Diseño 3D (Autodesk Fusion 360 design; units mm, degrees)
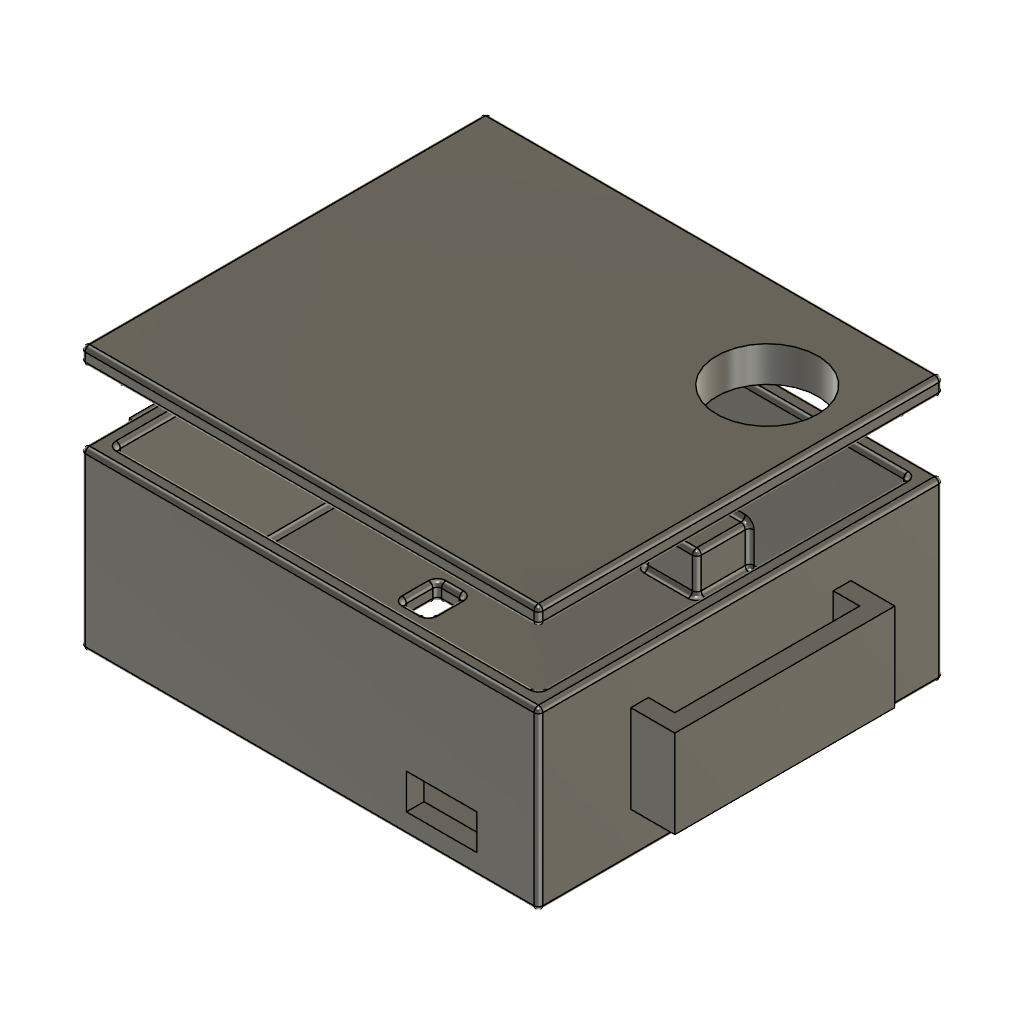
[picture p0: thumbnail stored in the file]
part number: 2026-10-19-01-26-55-343
sketch "Boceto1" plane through (0, 0, 0) normal (0, 0, 1) x axis (1, 0, 0)
  line L1 (-26, -23) -> (26, -23)
  line L2 (-26, 23) -> (-26, -23)
  line L3 (26, 23) -> (-26, 23)
  line L4 (26, -23) -> (26, 23)
  line L5 (-26, 23) -> (26, -23)
  line L6 (26, 23) -> (-26, -23)
  point P6 (0, 0)
  point P1 (0, 0)
  point P4 (-26, 23)
  point P5 (26, 23)
  point P3 (-26, -23)
  horizontal L1
  perpendicular L1 L2
  parallel L1 L3
  parallel L2 L4
  coincident L5 P6
  coincident L6 P6
  coincident P1 P6
  dimension "d1" distance P4 P5 = 52
  dimension "d2" distance P3 P4 = 46
extrude "Extruir1" new body sketch "Boceto1" profile of L1 L2 L3 L4 along normal blind 20
shell "Vaciado" innerThickness 2
sketch "Boceto2" plane through (0, 0, 2) normal (0, 0, 1) x axis (-1, 0, 0)
  line L1 (24, -21) -> (-24, -21)
  line L2 (24, 21) -> (24, -21)
  line L3 (-24, 21) -> (24, 21)
  line L4 (-24, -21) -> (-24, 21)
  line L5 (2, 1.5) -> (-2, 1.5)
  line L6 (2, -1.5) -> (2, 1.5)
  line L7 (-2, -1.5) -> (2, -1.5)
  line L8 (-2, 1.5) -> (-2, -1.5)
  line L9 (2, -1.5) -> (-2, 1.5)
  line L10 (-2, -1.5) -> (2, 1.5)
  point P10 (0, 0)
  point P1 (0, 0)
  point P8 (2, -1.5)
  point P9 (-2, -1.5)
  point P7 (2, 1.5)
  horizontal L5
  perpendicular L5 L6
  parallel L5 L7
  parallel L6 L8
  coincident L9 P10
  coincident L10 P10
  coincident P1 P10
  dimension "d6" distance P8 P9 = 4
  dimension "d7" distance P7 P8 = 3
sketch "Boceto3" plane through (0, 0, 2) normal (0, 0, 1) x axis (-1, 0, 0)
  line L1 (24, -21) -> (-24, -21)
  line L2 (24, 21) -> (24, -21)
  line L3 (-24, 21) -> (24, 21)
  line L4 (-24, -21) -> (-24, 21)
  line L5 (18, -21) -> (24, -21)
  line L6 (18, -15) -> (18, -21)
  line L7 (24, -15) -> (18, -15)
  line L8 (24, -21) -> (24, -15)
  point P3 (24, -21)
  point P6 (24, -21)
  point P7 (18, -21)
  point P9 (24, -15)
  horizontal L5
  vertical L6
  horizontal L7
  vertical L8
  coincident P3 P6
  dimension "d10" distance P6 P7 = 6
  dimension "d11" distance P6 P9 = 6
sketch "Boceto4" plane through (0, 0, 2) normal (0, 0, 1) x axis (-1, 0, 0)
  line L1 (18, 21) -> (24, 21)
  line L2 (18, 15) -> (18, 21)
  line L3 (24, 15) -> (18, 15)
  line L4 (24, 21) -> (24, 15)
  point P2 (24, 21)
  point P3 (18, 21)
  point P5 (24, 15)
  horizontal L1
  vertical L2
  horizontal L3
  vertical L4
  dimension "d12" distance P2 P3 = 6
  dimension "d13" distance P2 P5 = 6
sketch "Boceto5" plane through (0, 0, 2) normal (0, 0, 1) x axis (-1, 0, 0)
sketch "Boceto8" plane through (0, 0, 2) normal (0, 0, 1) x axis (-1, 0, 0)
  line L1 (-24, 21) -> (24, 21)
  line L2 (-24, -21) -> (-24, 21)
  line L3 (24, -21) -> (-24, -21)
  line L4 (24, 21) -> (24, -21)
  line L5 (7.5, -2) -> (10.5, -2)
  line L6 (7.5, 2) -> (7.5, -2)
  line L7 (10.5, 2) -> (7.5, 2)
  line L8 (10.5, -2) -> (10.5, 2)
  point P8 (10.5, -2)
  point P9 (7.5, -2)
  point P11 (10.5, 2)
  horizontal L5
  vertical L6
  horizontal L7
  vertical L8
  dimension "d16" distance P8 P9 = 3
  dimension "d17" distance P8 P11 = 4
  dimension "d19" distance L4 L8 = 13.5
extrude "Extruir4" cut sketch "Boceto8" profile of L5 L6 L7 L8 against normal blind 2
sketch "Boceto9" plane through (0, 0, 2) normal (0, 0, 1) x axis (-1, 0, 0)
  line L1 (7.5, 2) -> (7.5, -2)
  line L2 (10.5, 2) -> (7.5, 2)
  line L3 (10.5, -2) -> (10.5, 2)
  line L4 (7.5, -2) -> (10.5, -2)
  line L5 (24, -21) -> (-24, -21)
  line L6 (24, 21) -> (24, -21)
  line L7 (-24, 21) -> (24, 21)
  line L8 (-24, -21) -> (-24, 21)
  line L9 (18, -21) -> (24, -21)
  line L10 (18, -15) -> (18, -21)
  line L11 (24, -15) -> (18, -15)
  line L12 (24, -21) -> (24, -15)
  point P7 (24, -21)
  point P10 (24, -21)
  horizontal L9
  vertical L10
  horizontal L11
  vertical L12
  coincident P7 P10
sketch "Boceto10" plane through (0, 0, 2) normal (0, 0, 1) x axis (-1, 0, 0)
  line L1 (18, 21) -> (24, 21)
  line L2 (18, 15) -> (18, 21)
  line L3 (24, 15) -> (18, 15)
  line L4 (24, 21) -> (24, 15)
  horizontal L1
  vertical L2
  horizontal L3
  vertical L4
sketch "Boceto11" plane through (0, 0, 2) normal (0, 0, 1) x axis (-1, 0, 0)
  line L1 (-6, -21) -> (0, -21)
  line L2 (-6, -15) -> (-6, -21)
  line L3 (0, -15) -> (-6, -15)
  line L4 (0, -21) -> (0, -15)
  line L5 (18, -15) -> (18, -21)
  horizontal L1
  vertical L2
  horizontal L3
  vertical L4
  dimension "d23" distance L4 L5 = 18
sketch "Boceto12" plane through (0, 0, 2) normal (0, 0, 1) x axis (-1, 0, 0)
  line L1 (0, 21) -> (-6, 21)
  line L2 (0, 15) -> (0, 21)
  line L3 (-6, 15) -> (0, 15)
  line L4 (-6, 21) -> (-6, 15)
  line L5 (18, 15) -> (18, 21)
  horizontal L1
  vertical L2
  horizontal L3
  vertical L4
  dimension "d24" distance L2 L5 = 18
extrude "Extruir5" add blind 4.5
sketch "Boceto14" plane through (0, 0, 2) normal (0, 0, 1) x axis (-1, 0, 0)
  line L1 (0, 15) -> (0, 21)
  line L2 (-6, 15) -> (0, 15)
  line L3 (-6, 21) -> (-6, 15)
  line L4 (-24, 21) -> (-6, 21)
  line L5 (-24, -21) -> (-24, 21)
  line L6 (-6, -21) -> (-24, -21)
  line L7 (-6, -15) -> (-6, -21)
  line L8 (0, -15) -> (-6, -15)
  line L9 (0, -21) -> (0, -15)
  line L10 (18, -21) -> (0, -21)
  line L11 (18, -15) -> (18, -21)
  line L12 (24, -15) -> (18, -15)
  line L13 (24, 15) -> (24, -15)
  line L14 (18, 15) -> (24, 15)
  line L15 (18, 21) -> (18, 15)
  line L16 (0, 21) -> (18, 21)
  line L17 (7.5, 2) -> (7.5, -2)
  line L18 (10.5, 2) -> (7.5, 2)
  line L19 (10.5, -2) -> (10.5, 2)
  line L20 (7.5, -2) -> (10.5, -2)
  line L21 (-10, -21) -> (-24, -21)
  line L22 (-10, -3) -> (-10, -21)
  line L23 (-24, -3) -> (-10, -3)
  line L24 (-24, -21) -> (-24, -3)
  point P7 (-24, -21)
  point P22 (-24, -21)
  point P23 (-10, -21)
  horizontal L21
  vertical L22
  horizontal L23
  vertical L24
  coincident P7 P22
  dimension "d29" distance P22 P23 = 14
extrude "Extruir6" add sketch "Boceto14" profile of L5 L6 L21 L22 L23 L24 along normal blind 3
sketch "Boceto16" plane through (0, 0, 20) normal (0, 0, 1) x axis (-1, 0, 0)
  line L1 (-24, 21) -> (-24, -21)
  line L2 (24, 21) -> (-24, 21)
  line L3 (24, -21) -> (24, 21)
  line L4 (-24, -21) -> (24, -21)
  line L5 (26, -23) -> (-26, -23)
  line L6 (26, 23) -> (26, -23)
  line L7 (-26, 23) -> (26, 23)
  line L8 (-26, -23) -> (-26, 23)
extrude "Extruir7" new body sketch "Boceto16" profile of L1 L2 L3 L4 against normal blind 2
extrude "Extruir8" add sketch "Boceto16" along normal blind 2
fillet "Empalme" radius 0.5
move "Desplazar"
sketch "Boceto17" plane through (0, 0, 30) normal (0, 0, 1) x axis (-1, 0, 0)
  line L1 (25.5, 22.5) -> (25.5, -22.5)
  line L2 (-25.5, 22.5) -> (25.5, 22.5)
  line L3 (-25.5, -22.5) -> (-25.5, 22.5)
  line L4 (25.5, -22.5) -> (-25.5, -22.5)
  circle C1 centre (-17, -12) radius 5.75
  dimension "d38" diameter C1 = 11.5
extrude "Extruir9" cut sketch "Boceto17" profile of C1 against normal blind 5
sketch "Boceto18" plane through (26, 0, 0) normal (1, 0, 0) x axis (0, 1, 0)
  line L1 (22.5, 19.5) -> (22.5, 0.5)
  line L2 (-22.5, 19.5) -> (22.5, 19.5)
  line L3 (22.5, 0.5) -> (-22.5, 0.5)
  line L4 (12.5, 15) -> (-12.5, 15)
  line L5 (12.5, 5) -> (12.5, 15)
  line L6 (-12.5, 5) -> (12.5, 5)
  line L7 (-12.5, 15) -> (-12.5, 5)
  point P6 (-12.5, 15)
  point P7 (12.5, 15)
  point P9 (-12.5, 5)
  horizontal L4
  vertical L5
  horizontal L6
  vertical L7
  dimension "d41" distance P6 P7 = 25
  dimension "d43" distance L2 L4 = 4.5
  dimension "d44" distance P6 P9 = 10
  dimension "d45" distance L1 L5 = 10
extrude "Extruir10" add sketch "Boceto18" profile of L4 L5 L6 L7 along normal blind 5
sketch "Boceto21" plane through (0, 0, 15) normal (0, 0, 1) x axis (-1, 0, 0)
  line L1 (-26, 12.5) -> (-26, -12.5)
  line L2 (-31, 12.5) -> (-26, 12.5)
  line L3 (-31, -12.5) -> (-31, 12.5)
  line L4 (-26, -12.5) -> (-31, -12.5)
  line L5 (-29, -10.5) -> (-26, -10.5)
  line L6 (-29, 10.5) -> (-29, -10.5)
  line L7 (-26, 10.5) -> (-29, 10.5)
  line L8 (-26, -10.5) -> (-26, 10.5)
  point P6 (-26, -10.5)
  point P7 (-29, -10.5)
  point P9 (-26, 10.5)
  horizontal L5
  vertical L6
  horizontal L7
  vertical L8
  coincident L1 P6
  dimension "d48" distance P6 P7 = 3
  dimension "d49" distance P6 P9 = 21
  dimension "d50" distance L4 L5 = 2
extrude "Extruir11" cut sketch "Boceto21" profile of L1 L5 L6 L7 L8 against normal blind 11
sketch "Boceto22" plane through (-26, 0, 0) normal (-1, 0, 0) x axis (0, -1, 0)
  line L1 (22.5, 0.5) -> (-22.5, 0.5)
  line L2 (22.5, 19.5) -> (22.5, 0.5)
  line L3 (-22.5, 19.5) -> (22.5, 19.5)
  line L4 (-22.5, 0.5) -> (-22.5, 19.5)
  line L5 (12.5, 15) -> (-12.5, 15)
  line L6 (12.5, 5) -> (12.5, 15)
  line L7 (-12.5, 5) -> (12.5, 5)
  line L8 (-12.5, 15) -> (-12.5, 5)
  point P6 (-12.5, 15)
  point P7 (12.5, 15)
  point P9 (-12.5, 5)
  horizontal L5
  vertical L6
  horizontal L7
  vertical L8
  dimension "d53" distance P6 P7 = 25
  dimension "d54" distance P6 P9 = 10
  dimension "d55" distance L3 L5 = 4.5
  dimension "d56" distance L2 L6 = 10
extrude "Extruir12" add sketch "Boceto22" profile of L5 L6 L7 L8 along normal blind 5
sketch "Boceto23" plane through (0, 0, 15) normal (0, 0, 1) x axis (-1, 0, 0)
  line L1 (26, -12.5) -> (26, 12.5)
  line L2 (31, -12.5) -> (26, -12.5)
  line L3 (31, 12.5) -> (31, -12.5)
  line L4 (26, 12.5) -> (31, 12.5)
  line L5 (29, 10.5) -> (26, 10.5)
  line L6 (29, -10.5) -> (29, 10.5)
  line L7 (26, -10.5) -> (29, -10.5)
  line L8 (26, 10.5) -> (26, -10.5)
  point P6 (26, 10.5)
  horizontal L5
  vertical L6
  horizontal L7
  vertical L8
  coincident L1 P6
  dimension "d59" distance L4 L5 = 2
extrude "Extruir13" cut sketch "Boceto23" profile of L1 L5 L6 L7 L8 against normal blind 11
sketch "Boceto24" plane through (0, -21, 0) normal (0, 1, 0) x axis (-1, 0, 0)
  line L1 (-23.5, 19.5) -> (23.5, 19.5)
  line L2 (-23.5, 2.5) -> (-23.5, 19.5)
  line L3 (-6.5, 2.5) -> (-23.5, 2.5)
  line L4 (-6.5, 6) -> (-6.5, 2.5)
  line L5 (-0.5, 7) -> (-5.5, 7)
  line L6 (0.5, 2.5) -> (0.5, 6)
  line L7 (17.5, 2.5) -> (0.5, 2.5)
  line L8 (17.5, 6) -> (17.5, 2.5)
  line L9 (23.5, 7) -> (18.5, 7)
  line L10 (23.5, 19.5) -> (23.5, 7)
  line L11 (-11, 2.5) -> (-19, 2.5)
  line L12 (-11, 6.5) -> (-11, 2.5)
  line L13 (-19, 6.5) -> (-11, 6.5)
  line L14 (-19, 2.5) -> (-19, 6.5)
  arc A1 centre (-5.5, 6) radius 1 clockwise from (-6.5, 6) to (-5.5, 7)
  arc A2 centre (-0.5, 6) radius 1 clockwise from (-0.5, 7) to (0.5, 6)
  arc A3 centre (18.5, 6) radius 1 clockwise from (17.5, 6) to (18.5, 7)
  point P18 (-19, 2.5)
  point P19 (-11, 2.5)
  point P21 (-19, 6.5)
  horizontal L11
  vertical L12
  horizontal L13
  vertical L14
  coincident L3 P18
  dimension "d62" distance P18 P19 = 8
  dimension "d63" distance P18 P21 = 4
  dimension "d64" distance L2 L14 = 4.5
extrude "Extruir14" cut sketch "Boceto24" profile of L3 L11 L12 L13 L14 against normal blind 3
